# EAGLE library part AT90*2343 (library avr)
MICROCONTROLLER 2 Kbytes FLASH 128 bytes SRAM 128 bytes EEPROM
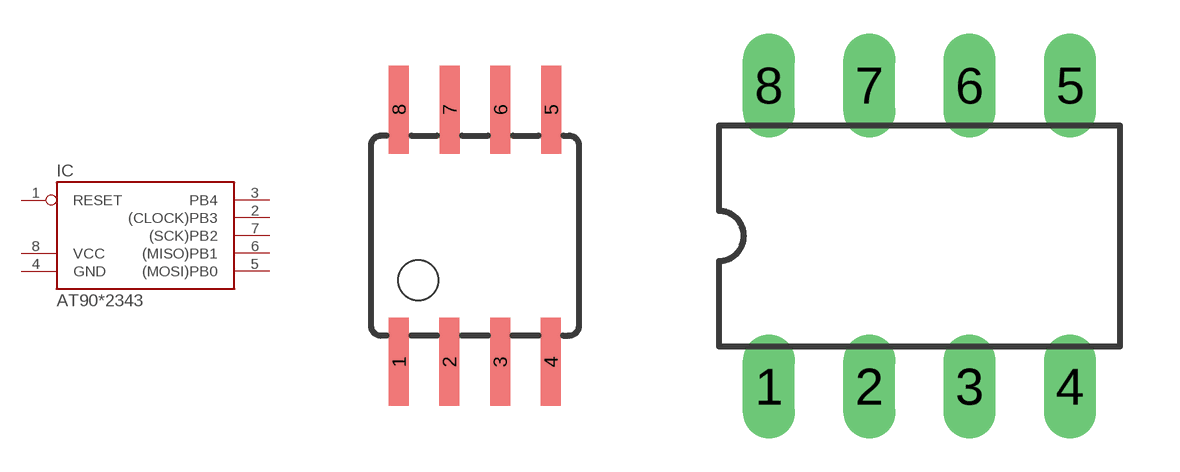
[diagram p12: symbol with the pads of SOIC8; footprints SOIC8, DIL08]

Designator prefix IC

## AT90LS2343S, AT90S2343S  [SOIC8]
1  RESET  in
2  (CLOCK)PB3
3  PB4
4  GND  pwr
5  (MOSI)PB0
6  (MISO)PB1
7  (SCK)PB2
8  VCC  pwr

## AT90LS2343P, AT90S2343P  [DIL08]
Pads as for SOIC8

## Footprint SOIC8 (pad centres in mm)
Wide Plastic Gull Wing Small Outline Package
smd 0.5 x 2.2: 1 -1.905,-3.154; 2 -0.645,-3.154; 3 0.625,-3.154; 4 1.895,-3.154; 5 1.905,3.154; 6 0.635,3.154; 7 -0.635,3.154; 8 -1.905,3.154

## Footprint DIL08 (pad centres in mm)
Dual In Line
drill 0.813 long: 1 -3.81,-3.81; 2 -1.27,-3.81; 3 1.27,-3.81; 4 3.81,-3.81; 5 3.81,3.81; 6 1.27,3.81; 7 -1.27,3.81; 8 -3.81,3.81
